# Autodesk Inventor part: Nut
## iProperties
Shininess: 77.0
Length Units: 11269
Angle Units: 11279
Time Units: 11290
Mass Units: 11283
Length Display Precision: 3
Angle Display Precision: 2
Created: 2002-01
Part Number: Nut
Document SubType Name: Modeling
Designer: ***
Density: 0.0
Volumn: 0.0
Area: 0.0
PropertySet Name: Model Information
Control State: 0
Master: False
Checked Out: False
Author: ***
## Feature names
1. Extrusion1
2. Fillet1
3. Extrusion2
